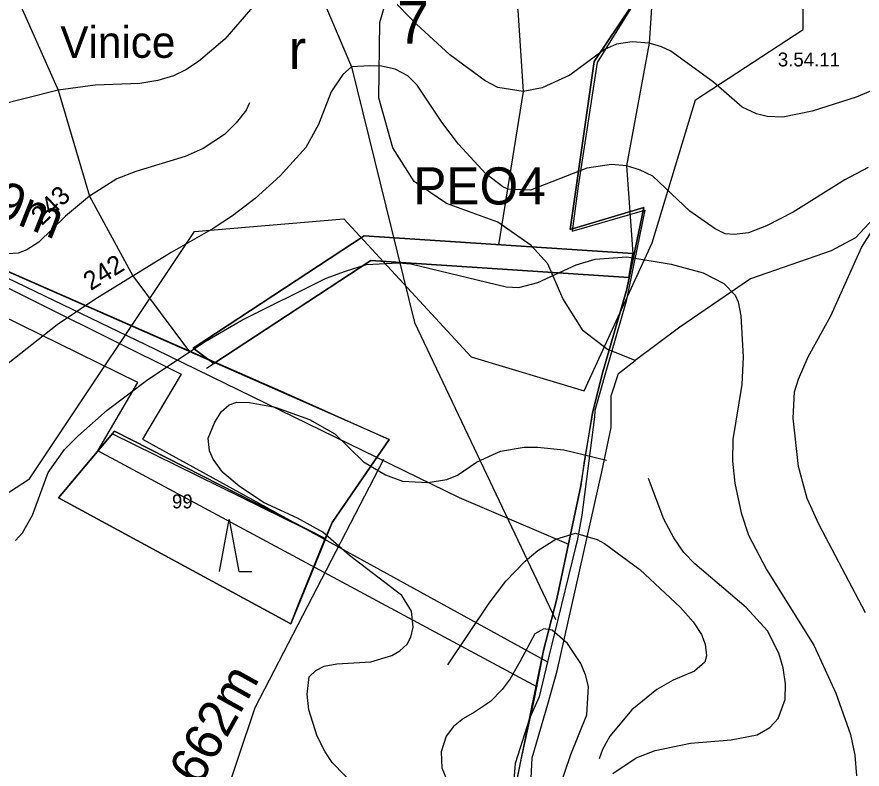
# Model space of a CAD drawing. Extents: x -662500 to -653478, y -1056827 to -1049993.
# Drawn here: x -659688.8 to -659233.9, y -1052767 to -1052362 of the extents above; entities that cross this region are included whole.
import ezdxf

# ---------------------------------------------------------------- set-up
doc = ezdxf.new("R2010")
doc.units = 0
for name, color, linetype in [('58', 7, 'Continuous'), ('Vrstva 1', 7, 'Continuous'), ('Vrstva 12', 7, 'Continuous'), ('Vrstva 15', 7, 'Continuous'), ('Vrstva 16', 7, 'Continuous'), ('Vrstva 18', 7, 'Continuous'), ('Vrstva 22', 7, 'Continuous'), ('Vrstva 24', 7, 'Continuous'), ('Vrstva 35', 7, 'Continuous'), ('Vrstva 36', 7, 'Continuous'), ('Vrstva 37', 7, 'Continuous'), ('Vrstva 5', 7, 'Continuous'), ('Vrstva 51', 7, 'Continuous'), ('Vrstva 57', 7, 'Continuous'), ('Vrstva 6', 7, 'Continuous'), ('Vrstva 7', 7, 'Continuous')]:
    doc.layers.add(name, color=color, linetype=linetype)

msp = doc.modelspace()

# ---------------------------------------------------------------- linework, layer by layer
at = {"layer": '58'}
msp.add_lwpolyline([(-659351.19, -1052345.64), (-659376.51, -1052386.45), (-659386.77, -1052453.16), (-659389.91, -1052477.37), (-659350.86, -1052466.04), (-659360.95, -1052515.07), (-659372.04, -1052553.55), (-659377.67, -1052573.87), (-659378, -1052577.29), (-659384.78, -1052630.2), (-659387.27, -1052644.16), (-659388.08, -1052647.48), (-659403.17, -1052709.23), (-659407.79, -1052728.1), (-659412.92, -1052739.74), (-659420.7, -1052763.94), (-659421.56, -1052774.88)], dxfattribs=at)
at = {"layer": 'Vrstva 1'}
msp.add_line((-659666.36, -1052620.96), (-659656, -1052608.58), dxfattribs=at)
for points in [[(-659351.57, -1052346.35), (-659378.02, -1052386.02), (-659390.97, -1052476.36), (-659351.38, -1052464.53), (-659360.53, -1052508.64), (-659373.81, -1052554.38), (-659378.95, -1052575.38), (-659383.52, -1052601.23), (-659385.35, -1052614.38), (-659398.17, -1052675.24), (-659405.34, -1052703.15), (-659410.42, -1052729.16), (-659417.6, -1052762.04), (-659426.9, -1052808.74)], [(-659656, -1052608.58), (-659636.28, -1052585.02), (-659522.86, -1052642.76), (-659537.13, -1052678.16)], [(-659666.36, -1052620.96), (-659541.43, -1052688.68), (-659537.13, -1052678.16)]]:
    msp.add_lwpolyline(points, dxfattribs=at)
at = {"layer": 'Vrstva 12'}
msp.add_lwpolyline([(-659975.22, -1052363.23), (-659957.91, -1052372.73), (-659920.43, -1052396.6), (-659893.12, -1052405.51), (-659744.12, -1052478.37), (-659614.29, -1052540.87), (-659450.8, -1052620.7), (-659391.97, -1052645.81)], dxfattribs=at)
at = {"layer": 'Vrstva 15'}
msp.add_lwpolyline([(-659491.47, -1052600.22), (-659560.64, -1052733.92), (-659579.45, -1052789.58), (-659610.72, -1052846.89), (-659556.93, -1052891.69), (-659532.56, -1052924.18), (-659546.19, -1053014.6), (-659577.15, -1053106.27), (-659597.46, -1053161.91), (-659614.21, -1053201.5)], dxfattribs=at)
at = {"layer": 'Vrstva 22'}
for p, q in [((-659593.87, -1052540.3), (-659501.85, -1052479.81)), ((-659586.73, -1052551.16), (-659498.36, -1052493.07))]:
    msp.add_line(p, q, dxfattribs=at)
msp.add_lwpolyline([(-659593.87, -1052540.3), (-659501.85, -1052479.81), (-659357.23, -1052489.43), (-659359.52, -1052502.31), (-659498.36, -1052493.07), (-659582.78, -1052548.57)], close=True, dxfattribs=at)
at = {"layer": 'Vrstva 24'}
for points in [[(-659356, -1052547), (-659369.9, -1052541.44), (-659371, -1052541), (-659384, -1052531), (-659395, -1052513.5), (-659403, -1052495), (-659412, -1052485), (-659430, -1052472.5), (-659457.5, -1052462.5), (-659475, -1052450.5), (-659486.5, -1052432.5), (-659494, -1052405.5), (-659493.5, -1052365), (-659487, -1052342.5), (-659471.5, -1052315.5), (-659450, -1052297), (-659443, -1052294)], [(-659091, -1052506), (-659218, -1052460), (-659237.5, -1052481), (-659250.5, -1052488), (-659294, -1052503), (-659332, -1052529), (-659356, -1052547)], [(-659432, -1052926), (-659430.5, -1052919), (-659432.03, -1052911.34), (-659433, -1052906.5), (-659431, -1052848), (-659428, -1052826), (-659421.5, -1052819.5), (-659413.5, -1052801.5), (-659411.5, -1052761), (-659403, -1052732), (-659398, -1052714), (-659374, -1052607), (-659369, -1052583), (-659369, -1052566), (-659365, -1052554), (-659356, -1052547)]]:
    msp.add_lwpolyline(points, dxfattribs=at)
msp.add_lwpolyline([(-659522.86, -1052642.76), (-659636.28, -1052585.02), (-659656, -1052608.58), (-659666.36, -1052620.96), (-659541.43, -1052688.68), (-659537.13, -1052678.16)], close=True, dxfattribs=at)
at = {"layer": 'Vrstva 35'}
msp.add_lwpolyline([(-659447.57, -1052234.77), (-659449.34, -1052252.16), (-659433.96, -1052302.14), (-659419.16, -1052358.38), (-659416.31, -1052402.09), (-659429.54, -1052484.62)], dxfattribs=at)
at = {"layer": 'Vrstva 36'}
for points in [[(-659390.32, -1052019.34), (-659473.97, -1052032.46), (-659523.65, -1052033.38), (-659629.9, -1052027.09), (-659621.04, -1052067.57), (-659612.63, -1052095.78), (-659613.06, -1052104.19), (-659616.18, -1052110.87), (-659620.93, -1052116.23), (-659629.5, -1052120.84), (-659671.87, -1052141.1), (-659688.36, -1052149.79), (-659691.31, -1052152.96), (-659692.79, -1052159.14), (-659681.03, -1052192.1), (-659680.96, -1052200.79), (-659688.64, -1052239.7), (-659719.21, -1052284.92), (-659707.09, -1052314.99), (-659690.29, -1052347.87), (-659666.49, -1052401.44), (-659649.62, -1052458.41), (-659626.31, -1052501.42), (-659596.35, -1052541.51)], [(-659390.32, -1052019.34), (-659379.29, -1052053.33), (-659372.74, -1052085.93), (-659368.18, -1052102.67), (-659352.52, -1052124.73), (-659340.85, -1052146.73), (-659310.45, -1052197.06), (-659327.75, -1052284.63), (-659330.67, -1052287.3), (-659345.12, -1052324.35), (-659348.54, -1052376.18), (-659360.78, -1052442.24), (-659357.23, -1052489.43)]]:
    msp.add_lwpolyline(points, dxfattribs=at)
at = {"layer": 'Vrstva 37'}
msp.add_lwpolyline([(-659725.21, -1052638.68), (-659681.94, -1052610.76), (-659593.13, -1052477.47), (-659512.86, -1052470.64), (-659444.33, -1052545.04), (-659383.41, -1052563.27), (-659346.98, -1052483.53), (-659323.49, -1052406.63), (-659265.71, -1052368.75), (-659265.71, -1052313.92), (-659298.73, -1052302.49), (-659368.75, -1052154.96), (-659417.14, -1052139.58), (-659488.88, -1052161.23), (-659509.37, -1052148.69), (-659509.37, -1052124.63), (-659530.01, -1052053.42), (-659514.64, -1052002.73), (-659551.64, -1051995.89), (-659673.12, -1052221.79), (-659730.97, -1052288.96)], dxfattribs=at)
at = {"layer": 'Vrstva 5'}
for points in [[(-659426.9, -1052808.74), (-659412.92, -1052739.74), (-659405.34, -1052703.15), (-659398.17, -1052675.24), (-659385.35, -1052614.38), (-659378.95, -1052575.38), (-659373.81, -1052554.38), (-659360.53, -1052508.64), (-659351.38, -1052464.53), (-659390.97, -1052476.36), (-659378.02, -1052386.02), (-659351.57, -1052346.35)], [(-659931.7, -1052394.49), (-659546.84, -1052563.39), (-659488.42, -1052589.49), (-659519.16, -1052634.21), (-659541.43, -1052688.68), (-659666.36, -1052620.96), (-659637.28, -1052586.47), (-659522.86, -1052642.76), (-659519.16, -1052634.21), (-659488.42, -1052589.49), (-659931.7, -1052394.49)], [(-659579.75, -1052660.56), (-659574.5, -1052632.56), (-659569.25, -1052660.56), (-659562.25, -1052660.56)]]:
    msp.add_lwpolyline(points, dxfattribs=at)
msp.add_lwpolyline([(-659666.36, -1052620.96), (-659636.28, -1052585.02), (-659522.86, -1052642.76), (-659541.43, -1052688.68)], close=True, dxfattribs=at)
at = {"layer": 'Vrstva 51'}
for points in [[(-660169.13, -1053023.13), (-660110.85, -1052940.58), (-660079.74, -1052916.29), (-659950.2, -1052798.66), (-659898.58, -1052720.65), (-659915.89, -1052669.98), (-659910.89, -1052596.38), (-659900.42, -1052552.71), (-659942.19, -1052387.83), (-659921.6, -1052399.48), (-659893.5, -1052409.43), (-659785.78, -1052462.16), (-659600.37, -1052554.27), (-659621.1, -1052589.25), (-659403.17, -1052709.23)], [(-659408.68, -1052722.85), (-659645.22, -1052595.6), (-659623.64, -1052558.85), (-659899.32, -1052423.28), (-659921, -1052417.16), (-659884.97, -1052552.61), (-659896.01, -1052598.65), (-659902.05, -1052660.61), (-659882, -1052722.78), (-659938.73, -1052808.5), (-660070.07, -1052927.77), (-660099.87, -1052951.04), (-660151.35, -1053023.96)]]:
    msp.add_lwpolyline(points, dxfattribs=at)
at = {"layer": 'Vrstva 57'}
msp.add_lwpolyline([(-659618.3, -1052043.89), (-659602.31, -1052104.35), (-659598.67, -1052138.3), (-659592.06, -1052165.06), (-659579.9, -1052186.97), (-659553.68, -1052246.68), (-659542.36, -1052285.96), (-659538.36, -1052313.22), (-659527.2, -1052345.29), (-659508.78, -1052388.91), (-659474.8, -1052526.47), (-659398.9, -1052686.49)], dxfattribs=at)
at = {"layer": 'Vrstva 6'}
msp.add_lwpolyline([(-659593.87, -1052540.3), (-659582.78, -1052548.57), (-659498.36, -1052493.07), (-659359.52, -1052502.31), (-659357.23, -1052489.43), (-659501.85, -1052479.81)], close=True, dxfattribs=at)
at = {"layer": 'Vrstva 7'}
for p, q in [((-659473.69, -1052365.93), (-659489.52, -1052349.71)), ((-659560.77, -1052355.24), (-659576.92, -1052373.94)), ((-659455.75, -1052382.44), (-659473.69, -1052365.93)), ((-659576.92, -1052373.94), (-659590.95, -1052385.99)), ((-659366.05, -1052376.6), (-659372.46, -1052379.45)), ((-659357.65, -1052375.32), (-659366.05, -1052376.6)), ((-659348.54, -1052376.18), (-659357.65, -1052375.32)), ((-659341.84, -1052378.03), (-659348.54, -1052376.18)), ((-659372.46, -1052379.45), (-659391.25, -1052393.41)), ((-659336.86, -1052380.45), (-659341.84, -1052378.03)), ((-659313.94, -1052397.11), (-659336.86, -1052380.45)), ((-659590.95, -1052385.99), (-659597.89, -1052390.52)), ((-659436.81, -1052396.4), (-659455.75, -1052382.44)), ((-659597.89, -1052390.52), (-659604.41, -1052393.64)), ((-659508.78, -1052388.91), (-659513.34, -1052392.95)), ((-659498.84, -1052388.26), (-659508.78, -1052388.91)), ((-659492.62, -1052388.56), (-659498.84, -1052388.26)), ((-659485.22, -1052390.13), (-659492.62, -1052388.56)), ((-659478.39, -1052393.69), (-659485.22, -1052390.13)), ((-659604.41, -1052393.64), (-659612.92, -1052396.19)), ((-659513.34, -1052392.95), (-659519.67, -1052402.29)), ((-659473.4, -1052398.67), (-659478.39, -1052393.69)), ((-659391.25, -1052393.41), (-659406.06, -1052400.24)), ((-659646.65, -1052398.74), (-659666.49, -1052401.44)), ((-659622.55, -1052397.75), (-659646.65, -1052398.74)), ((-659612.92, -1052396.19), (-659622.55, -1052397.75)), ((-659460.16, -1052418.61), (-659473.4, -1052398.67)), ((-659429.98, -1052399.96), (-659436.81, -1052396.4)), ((-659416.31, -1052402.09), (-659429.98, -1052399.96)), ((-659406.06, -1052400.24), (-659416.31, -1052402.09)), ((-659298.42, -1052410.49), (-659313.94, -1052397.11)), ((-659224.67, -1052399.96), (-659237.05, -1052405.22)), ((-659666.49, -1052401.44), (-659703.05, -1052410.51)), ((-659519.67, -1052402.29), (-659526.47, -1052419.86)), ((-659565.16, -1052411.92), (-659563.32, -1052408.1)), ((-659237.05, -1052405.22), (-659260.83, -1052412.63)), ((-659565.16, -1052411.92), (-659570.69, -1052419.01)), ((-659290.73, -1052414.19), (-659298.42, -1052410.49)), ((-659260.83, -1052412.63), (-659276.49, -1052415.9)), ((-659285.03, -1052415.62), (-659290.73, -1052414.19)), ((-659276.49, -1052415.9), (-659285.03, -1052415.62)), ((-659570.69, -1052419.01), (-659577.06, -1052425.24)), ((-659526.47, -1052419.86), (-659533.27, -1052432.19)), ((-659451.19, -1052430.57), (-659460.16, -1052418.61)), ((-659577.06, -1052425.24), (-659588.54, -1052432.76)), ((-659436.39, -1052446.51), (-659451.19, -1052430.57)), ((-659588.54, -1052432.76), (-659598.18, -1052437.15)), ((-659533.27, -1052432.19), (-659547.02, -1052447.49)), ((-659598.18, -1052437.15), (-659624.82, -1052445.23)), ((-659624.82, -1052445.23), (-659635.03, -1052449.19)), ((-659382.14, -1052443.38), (-659412.32, -1052455.2)), ((-659368.75, -1052441.39), (-659382.14, -1052443.38)), ((-659360.78, -1052442.24), (-659368.75, -1052441.39)), ((-659353.66, -1052444.24), (-659360.78, -1052442.24)), ((-659346.54, -1052447.8), (-659353.66, -1052444.24)), ((-659230.65, -1052443.1), (-659243.17, -1052449.65)), ((-659635.03, -1052449.19), (-659649.62, -1052458.41)), ((-659547.02, -1052447.49), (-659560.62, -1052459.68)), ((-659427.27, -1052453.49), (-659436.39, -1052446.51)), ((-659326.61, -1052466.59), (-659346.54, -1052447.8)), ((-659243.17, -1052449.65), (-659270.94, -1052467.16)), ((-659424.57, -1052454.63), (-659427.27, -1052453.49)), ((-659412.32, -1052455.2), (-659424.57, -1052454.63)), ((-659649.62, -1052458.41), (-659662.52, -1052469.32)), ((-659560.62, -1052459.68), (-659572.81, -1052469.03)), ((-659312.94, -1052476.13), (-659326.61, -1052466.59)), ((-659270.94, -1052467.16), (-659285.32, -1052474.42)), ((-659662.52, -1052469.32), (-659676.97, -1052483.21)), ((-659572.81, -1052469.03), (-659583.16, -1052475.84)), ((-659583.16, -1052475.84), (-659605.83, -1052488.73)), ((-659307.53, -1052478.83), (-659312.94, -1052476.13)), ((-659285.32, -1052474.42), (-659295, -1052478.27)), ((-659234.2, -1052486.1), (-659228.65, -1052477.41)), ((-659302.69, -1052479.12), (-659307.53, -1052478.83)), ((-659295, -1052478.27), (-659302.69, -1052479.12)), ((-659676.97, -1052483.21), (-659683.49, -1052487.32)), ((-659250.72, -1052522.83), (-659234.2, -1052486.1)), ((-659688.03, -1052489.16), (-659702.91, -1052490.15)), ((-659683.49, -1052487.32), (-659688.03, -1052489.16)), ((-659605.83, -1052488.73), (-659646.79, -1052514.1)), ((-659377.58, -1052492.36), (-659360.5, -1052491.08)), ((-659360.5, -1052491.08), (-659336.58, -1052495.07)), ((-659512.01, -1052498.8), (-659500.6, -1052495.35)), ((-659500.6, -1052495.35), (-659483.51, -1052494.35)), ((-659483.51, -1052494.35), (-659476.68, -1052494.92)), ((-659476.68, -1052494.92), (-659425.42, -1052507.31)), ((-659408.34, -1052505.03), (-659387.83, -1052495.49)), ((-659387.83, -1052495.49), (-659377.58, -1052492.36)), ((-659336.58, -1052495.07), (-659319.49, -1052499.77)), ((-659522.33, -1052502.66), (-659512.01, -1052498.8)), ((-659319.49, -1052499.77), (-659308.24, -1052505.46)), ((-659567.73, -1052525.31), (-659522.33, -1052502.66)), ((-659425.42, -1052507.31), (-659418.59, -1052507.59)), ((-659418.59, -1052507.59), (-659408.34, -1052505.03)), ((-659308.24, -1052505.46), (-659302.26, -1052511.73)), ((-659302.26, -1052511.73), (-659300.7, -1052515.43)), ((-659646.79, -1052514.1), (-659667.05, -1052527.71)), ((-659300.7, -1052515.43), (-659299.13, -1052522.83)), ((-659299.13, -1052522.83), (-659297.99, -1052545.04)), ((-659262.96, -1052545.04), (-659250.72, -1052522.83)), ((-659587.41, -1052536.77), (-659567.73, -1052525.31)), ((-659667.05, -1052527.71), (-659696.95, -1052551.23)), ((-659618.3, -1052557.18), (-659587.41, -1052536.77)), ((-659297.99, -1052545.04), (-659298.7, -1052559.85)), ((-659268.23, -1052557), (-659262.96, -1052545.04)), ((-659640.13, -1052573.76), (-659618.3, -1052557.18)), ((-659270.37, -1052563.84), (-659268.23, -1052557)), ((-659298.7, -1052559.85), (-659303.4, -1052589.47)), ((-659271.08, -1052578.07), (-659270.37, -1052563.84)), ((-659578.91, -1052574.61), (-659574.51, -1052570.79)), ((-659574.51, -1052570.79), (-659570.4, -1052569.37)), ((-659570.4, -1052569.37), (-659563.6, -1052569.51)), ((-659563.6, -1052569.51), (-659549.71, -1052572.06)), ((-659549.71, -1052572.06), (-659531.38, -1052578.67)), ((-659656, -1052587.65), (-659640.13, -1052573.76)), ((-659582.45, -1052580.56), (-659578.91, -1052574.61)), ((-659585.85, -1052588.78), (-659582.45, -1052580.56)), ((-659531.38, -1052578.67), (-659517.67, -1052586.43)), ((-659268.23, -1052603.99), (-659271.08, -1052578.07)), ((-659517.67, -1052586.43), (-659502.16, -1052601.57)), ((-659663.08, -1052594.88), (-659656, -1052587.65)), ((-659585.14, -1052595.59), (-659585.85, -1052588.78)), ((-659303.4, -1052589.47), (-659303.69, -1052601.14)), ((-659671.87, -1052607.21), (-659663.08, -1052594.88)), ((-659583.16, -1052600.12), (-659585.14, -1052595.59)), ((-659428.55, -1052595.87), (-659415.74, -1052593.59)), ((-659415.74, -1052593.59), (-659408.62, -1052593.59)), ((-659408.62, -1052593.59), (-659394.38, -1052595.16)), ((-659394.38, -1052595.16), (-659371.45, -1052600.57)), ((-659577.91, -1052607.21), (-659583.16, -1052600.12)), ((-659441.37, -1052601.71), (-659428.55, -1052595.87)), ((-659502.16, -1052601.57), (-659490.35, -1052608.54)), ((-659451.62, -1052608.69), (-659441.37, -1052601.71)), ((-659303.69, -1052601.14), (-659302.4, -1052613.1)), ((-659263.39, -1052621.36), (-659268.23, -1052603.99)), ((-659680.37, -1052630.31), (-659671.87, -1052607.21)), ((-659569.13, -1052614.72), (-659577.91, -1052607.21)), ((-659490.35, -1052608.54), (-659481.23, -1052611.96)), ((-659457.32, -1052610.96), (-659451.62, -1052608.69)), ((-659481.23, -1052611.96), (-659467.57, -1052612.67)), ((-659467.57, -1052612.67), (-659457.32, -1052610.96)), ((-659340.56, -1052632.46), (-659348.92, -1052610.55)), ((-659302.4, -1052613.1), (-659298.99, -1052629.05)), ((-659556.09, -1052623.47), (-659569.13, -1052614.72)), ((-659257.27, -1052635.03), (-659263.39, -1052621.36)), ((-659537.72, -1052631.9), (-659556.09, -1052623.47)), ((-659685.76, -1052639.8), (-659680.37, -1052630.31)), ((-659524.16, -1052639.42), (-659537.72, -1052631.9)), ((-659298.99, -1052629.05), (-659295, -1052641.01)), ((-659335.29, -1052642.43), (-659340.56, -1052632.46)), ((-659232.07, -1052682.87), (-659257.27, -1052635.03)), ((-659689.44, -1052643.91), (-659685.76, -1052639.8)), ((-659509.85, -1052651.97), (-659524.16, -1052639.42)), ((-659398.65, -1052643.14), (-659388.12, -1052640.01)), ((-659388.12, -1052640.01), (-659376.58, -1052643.28)), ((-659295, -1052641.01), (-659285.32, -1052659.52)), ((-659408.34, -1052649.26), (-659398.65, -1052643.14)), ((-659376.58, -1052643.28), (-659372.46, -1052645.56)), ((-659372.46, -1052645.56), (-659353.52, -1052659.52)), ((-659329.88, -1052650.4), (-659335.29, -1052642.43)), ((-659415.17, -1052654.96), (-659408.34, -1052649.26)), ((-659323.9, -1052656.53), (-659329.88, -1052650.4)), ((-659481.52, -1052673.47), (-659509.85, -1052651.97)), ((-659425.56, -1052665.78), (-659415.17, -1052654.96)), ((-659353.52, -1052659.52), (-659331.73, -1052679.88)), ((-659296.28, -1052680.02), (-659323.9, -1052656.53)), ((-659285.32, -1052659.52), (-659259.97, -1052700.24)), ((-659434.68, -1052677.6), (-659425.56, -1052665.78)), ((-659476.39, -1052682.01), (-659481.52, -1052673.47)), ((-659456.89, -1052710.92), (-659434.68, -1052677.6)), ((-659475.54, -1052690.55), (-659476.39, -1052682.01)), ((-659331.73, -1052679.88), (-659324.76, -1052687.71)), ((-659284.75, -1052692.55), (-659296.28, -1052680.02)), ((-659476.68, -1052695.97), (-659475.54, -1052690.55)), ((-659324.76, -1052687.71), (-659320.34, -1052694.54)), ((-659410, -1052694.23), (-659418.06, -1052709.16)), ((-659405.2, -1052691.38), (-659410, -1052694.23)), ((-659400.71, -1052692.18), (-659405.2, -1052691.38)), ((-659392.54, -1052699.29), (-659400.71, -1052692.18)), ((-659320.34, -1052694.54), (-659318.35, -1052699.67)), ((-659278.77, -1052704.51), (-659284.75, -1052692.55)), ((-659482.66, -1052703.37), (-659478.81, -1052699.67)), ((-659478.81, -1052699.67), (-659476.68, -1052695.97)), ((-659385.33, -1052710.11), (-659392.54, -1052699.29)), ((-659318.35, -1052699.67), (-659317.64, -1052705.93)), ((-659259.97, -1052700.24), (-659248.02, -1052726.15)), ((-659486.93, -1052705.79), (-659482.66, -1052703.37)), ((-659276.35, -1052712.48), (-659278.77, -1052704.51)), ((-659516.55, -1052710.35), (-659498.32, -1052709.21)), ((-659498.32, -1052709.21), (-659486.93, -1052705.79)), ((-659418.06, -1052709.16), (-659423.28, -1052718.45)), ((-659318.49, -1052709.35), (-659324.05, -1052714.33)), ((-659317.64, -1052705.93), (-659318.49, -1052709.35)), ((-659531.49, -1052717.32), (-659527.94, -1052713.91)), ((-659527.94, -1052713.91), (-659523.38, -1052711.63)), ((-659523.38, -1052711.63), (-659516.55, -1052710.35)), ((-659382.78, -1052716.27), (-659385.33, -1052710.11)), ((-659275.21, -1052721.02), (-659276.35, -1052712.48)), ((-659532.63, -1052726.72), (-659531.49, -1052717.32)), ((-659423.28, -1052718.45), (-659427.67, -1052724.15)), ((-659381.12, -1052722.46), (-659382.78, -1052716.27)), ((-659324.05, -1052714.33), (-659335.58, -1052719.17)), ((-659382.09, -1052737.75), (-659381.12, -1052722.46)), ((-659335.58, -1052719.17), (-659344.41, -1052724.16)), ((-659275.35, -1052729.57), (-659275.21, -1052721.02)), ((-659531.64, -1052734.98), (-659532.63, -1052726.72)), ((-659427.67, -1052724.15), (-659433.92, -1052730.52)), ((-659344.41, -1052724.16), (-659357.79, -1052734.98)), ((-659248.02, -1052726.15), (-659240.18, -1052748.36)), ((-659433.92, -1052730.52), (-659442.52, -1052736.34)), ((-659279.05, -1052739.82), (-659275.35, -1052729.57)), ((-659527.22, -1052749.22), (-659531.64, -1052734.98)), ((-659442.52, -1052736.34), (-659448.49, -1052739.68)), ((-659357.79, -1052734.98), (-659369.61, -1052749.22)), ((-659448.49, -1052739.68), (-659453.76, -1052744.09)), ((-659390.68, -1052759.18), (-659382.09, -1052737.75)), ((-659283.61, -1052744.52), (-659279.05, -1052739.82)), ((-659453.76, -1052744.09), (-659457.74, -1052749.22)), ((-659290.45, -1052748.5), (-659283.61, -1052744.52)), ((-659522.95, -1052757.76), (-659527.22, -1052749.22)), ((-659457.74, -1052749.22), (-659460.45, -1052757.76)), ((-659369.61, -1052749.22), (-659373.67, -1052756.45)), ((-659304.4, -1052751.21), (-659290.45, -1052748.5)), ((-659240.18, -1052748.36), (-659237.76, -1052759.47)), ((-659345.26, -1052756.9), (-659326.33, -1052753.06)), ((-659326.33, -1052753.06), (-659304.4, -1052751.21)), ((-659519.11, -1052763.45), (-659522.95, -1052757.76)), ((-659460.45, -1052757.76), (-659460.16, -1052766.3)), ((-659398.23, -1052781.11), (-659390.68, -1052759.18)), ((-659373.67, -1052756.45), (-659375.49, -1052761.43)), ((-659355.51, -1052760.89), (-659345.26, -1052756.9)), ((-659237.76, -1052759.47), (-659236.91, -1052770.57)), ((-659504.44, -1052778.4), (-659519.11, -1052763.45)), ((-659368.04, -1052769.43), (-659355.51, -1052760.89)), ((-659460.16, -1052766.3), (-659450.77, -1052788.51))]:
    msp.add_line(p, q, dxfattribs=at)

# ---------------------------------------------------------------- texts
at = {"layer": '58'}
msp.add_text('Vinice', height=17, dxfattribs=at).set_placement((-659665.38, -1052384))
at = {"layer": 'Vrstva 16'}
msp.add_text('C19-662m', height=20, rotation=60.9495, dxfattribs=at).set_placement((-659618.56, -1052827.45))
at = {"layer": 'Vrstva 18'}
msp.add_text('C9-639m', height=20, rotation=338.3114, dxfattribs=at).set_placement((-659770.53, -1052441.22))
at = {"layer": 'Vrstva 22'}
msp.add_text('PEO4', height=20, rotation=360, dxfattribs=at).set_placement((-659475.47, -1052462.97))
at = {"layer": 'Vrstva 24'}
for s, p in [('3.54.11', (-659279.28, -1052388.63)), ('99', (-659605.32, -1052626.6))]:
    msp.add_text(s, height=7.5, dxfattribs=at).set_placement(p)
at = {"layer": 'Vrstva 5'}
msp.add_text('r', height=21, dxfattribs=at).set_placement((-659542.43, -1052390.07))
at = {"layer": 'Vrstva 57'}
msp.add_text('7', height=23, dxfattribs=at).set_placement((-659484.2, -1052376.31))
at = {"layer": 'Vrstva 7'}
for s, rotation, p in [('243', 43.852, (-659675.3, -1052474.66)), ('242', 31.7729, (-659649.03, -1052509.61))]:
    msp.add_text(s, height=10, rotation=rotation, dxfattribs=at).set_placement(p)

doc.saveas('drawing.dxf')
